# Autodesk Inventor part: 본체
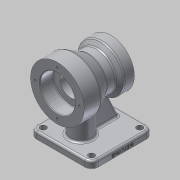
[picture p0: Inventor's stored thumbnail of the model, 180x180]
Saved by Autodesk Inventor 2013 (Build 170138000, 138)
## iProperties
Created: 2019-01
Part Number: 본체
Material: 알루미늄 6061
Document SubType Name: Modeling
Designer: Administrator
Density: 2.71 g/cm^3
Mass: 902.143 g
Surface Area: 600.963 cm^2
Volume: 332.894 cm^3
Author: Administrator
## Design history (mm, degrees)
sketch "스케치1"
  geometry: L1 (-46, 46)-(46, 46); L2 (46, 46)-(46, -46); L3 (46, -46)-(-46, -46); L4 (-46, -46)-(-46, 46); 3 further points
  constraints: 8 end point, 2 midpoint, 2 parallel, 1 horizontal, 1 horizontal alignment, 1 perpendicular, 1 vertical alignment
  dimensions: "d0" = 92 distance between parallel lines of L2 L4; "d2" = 92 distance between parallel lines of L3 L1
extrude "돌출1" new body sketch "스케치1" distance "d3" = 10; taper "d4" = 0 deg
sketch "스케치2"
  geometry: L1 (-51, 80)-(29, 80); L2 (46, 0)-(-46, 0) reference; L3 (-46, 0)-(-46, 10) reference; L4 (-51, 106)-(-51, 120); L5 (-51, 120)-(-26, 120); L6 (-26, 120)-(-5.215, 108); L7 (-5.215, 108)-(8.126, 108); L8 (8.126, 108)-(14, 115); L9 (14, 115)-(29, 115); L10 (29, 115)-(29, 100); L11 (-51, 106)-(-31, 106); L12 (-31, 106)-(-31, 96); L13 (-31, 96)-(12, 96); L14 (12, 96)-(12, 100); L15 (12, 100)-(29, 100); 1 further point
  constraints: 26 end point, 7 parallel, 3 perpendicular, 2 vertical alignment, 1 horizontal
  dimensions: "d5" = 80 distance between parallel lines of L2 L1; "d6" = 80 distance of L1.end L1.start; "d7" = 5 distance from line of L3 L1.start; "d8" = 17 distance between parallel lines of L10 L14; "d9" = 20 distance between parallel lines of L12 L4; "d10" = 56 diameter of L7 L1; "d12" = 80 diameter of L5 L1; "d13" = 70 diameter of L9 L1; "d14" = 50 deg angle of L7 L8; "d15" = 30 deg angle of L7 L6; "d16" = 25 distance of L4.end L5.end; "d17" = 15 distance of L9.end L8.end; "d18" = 40 diameter of L15 L1; "d19" = 32 diameter of L13 L1; "d20" = 52 diameter of L11 L1
revolve "회전1" sketch "스케치2" stored, may be unused: angle "d21" = 90 deg
fillet "모깎기1" dims "d22" = 1
fillet "모깎기2" dims "d23" = 0.6
chamfer "모따기1" distance "d24" = 1; stored, may be unused: second distance "d25" = 2, angle "d26" = 45 deg
fillet "모깎기3" dims "d27" = 3
sketch "스케치3"
  geometry: L1 (0, 33)-(0, -33); L2 (-33, 0)-(33, 0); C1 r 27 at (0, 0) reference; A1 r 33 centre (0, 0) between (0, 33) and (0, -33); 3 further points
  constraints: 4 end point, 4 point on circle, 2 midpoint, 1 centre point, 1 coincident, 1 horizontal alignment, 1 perpendicular, 1 vertical, 1 vertical alignment
  dimensions: "d28" = 66 diameter of A1
hole "구멍1" sketch "스케치3" at (0, 33), (33, 0), (0, -33), (-33, 0) diameter "d30" = 3.242; stored, may be unused: countersink angle "d34" = 90 deg, drill point angle "d36" = 118 deg; dims "d31" = 9, "d32" = 4, "d33" = 2, "d35" = 11
sketch "스케치4"
  geometry: L1 (0, 27.5)-(0, -27.5); L2 (-27.5, 0)-(27.5, 0); C1 r 35 at (0, 0) reference; C2 r 21 at (0, 0) reference; C3 r 1.621 at (0, -33) reference; A1 r 27.5 centre (0, 0) between (0, 27.5) and (0, -27.5); 3 further points
  constraints: 4 end point, 4 point on circle, 2 horizontal alignment, 1 centre point, 1 coincident, 1 midpoint, 1 perpendicular, 1 vertical, 1 vertical alignment
  dimensions: "d37" = 55 diameter of A1
hole "구멍2" sketch "스케치4" at (-27.5, 0), (0, 27.5), (27.5, 0), (0, -27.5) diameter "d40" = 3.242; stored, may be unused: countersink angle "d44" = 90 deg, drill point angle "d46" = 118 deg; dims "d41" = 9, "d42" = 4, "d43" = 2, "d45" = 11
sketch "스케치5"
  geometry: L1 (-46, -46)-(46, -46) reference; C1 r 16 at (0, -16); 1 further point
  constraints: 1 centre point, 1 vertical alignment
  dimensions: "d47" = 30 distance from line of L1 C1.centre; "d48" = 32 diameter of C1
extrude "돌출2" join sketch "스케치5" stored distance "d49" = 10; taper "d50" = 0 deg
sketch "스케치6"
  geometry: L1 (19.679, 45)-(36, 10); L2 (46, 10)-(-46, 10) reference; L3 (46, 0)-(46, 10) reference; L4 (15.399, 45)-(29, 45) reference; 1 further point
  constraints: 2 end point, 2 point on line
  dimensions: "d51" = 10 distance from line of L3 L1.end; "d52" = 25 deg angle of L3 L1
feature "리브1" sketch "스케치6" dims "d53" = 1, "d54" = 10, "d55" = 0, "d56" = 0, "d57" = 1, "d58" = 1
fillet "모깎기4" dims "d59" = 10
sketch "스케치7"
  geometry: C1 r 4.5 at (36, 36); C2 r 4.5 at (-36, 36); C3 r 4.5 at (-36, -36); C4 r 4.5 at (36, -36); A1 r 10 centre (-36, 36) between (-36, 46) and (-46, 36) reference; A2 r 10 centre (-36, -36) between (-46, -36) and (-36, -46) reference; A3 r 10 centre (36, -36) between (36, -46) and (46, -36) reference; A4 r 10 centre (36, 36) between (46, 36) and (36, 46) reference; 1 further point
  constraints: 4 centre point, 4 coincident, 3 equal radius
  dimensions: "d60" = 9 diameter of C1
extrude "돌출3" cut sketch "스케치7" stored distance "d62" = 10; taper "d63" = 0 deg
fillet "모깎기5" dims "d64" = 3
fillet "모깎기6" dims "d65" = 3
sketch "스케치8"
  geometry: L1 (-1.7, 4.031)-(-1.7, 67.969); L2 (-1.7, 67.969)-(-6.3, 67.969); L3 (-6.3, 67.969)-(-6.3, 4.031); L4 (-6.3, 4.031)-(-1.7, 4.031); L5 (-1.7, 36)-(-6.3, 36); L6 (-4, 67.969)-(-4, 4.031); L7 (-7, -10)-(0, -10) reference; 2 further points
  constraints: 4 end point, 4 midpoint, 2 other
  dimensions: "d66" = 46 distance from line of L7 L5.end; "d67" = 4 horizontal distance of point (0, 72) L6.start
feature "엠보싱1" sketch "스케치8" dims "d0" = 92, "d2" = 92, "d5" = 80, "d6" = 80, "d7" = 5, "d8" = 17, "d9" = 20, "d10" = 56, "d12" = 80, "d13" = 70, "d14" = 50 deg, "d15" = 30 deg, "d16" = 25, "d17" = 15, "d18" = 40, "d19" = 32, "d20" = 52, "d68" = 0.5, "d69" = 0
node "솔리드1"
